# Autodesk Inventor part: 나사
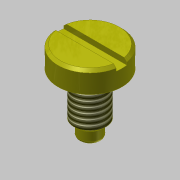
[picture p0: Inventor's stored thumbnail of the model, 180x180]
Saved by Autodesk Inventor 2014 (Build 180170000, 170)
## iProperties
Created: 2019-10
Part Number: 나사
Material: 스테인리스강
Document SubType Name: Modeling
Designer: mduedu
Density: 1 g/cm^3
Appearance: Yellow
Author: mduedu
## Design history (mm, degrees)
sketch "스케치1"
  geometry: L1 (0, 0)-(-6, 0); L2 (-6, 0)-(-6, -4); L3 (-6, -4)-(0, -4); L4 (0, -4)-(0, 0); L5 (0, -4)-(-3, -4); L6 (-3, -4)-(-3, -12.5); L7 (-3, -12.5)-(0, -12.5); L8 (0, -12.5)-(0, -4); L9 (0, -12.5)-(-2, -12.5); L10 (-2, -12.5)-(-2, -15); L11 (-2, -15)-(0, -15); L12 (0, -15)-(0, -12.5)
  constraints: 24 end point, 6 parallel, 3 horizontal, 3 perpendicular
  dimensions: "d0" = 15 distance between parallel lines of L11 L1; "d2" = 4 distance of L1.end L2.end; "d3" = 2.5 distance of L9.end L10.end; "d4" = 12 diameter of L2 L4; "d5" = 6 diameter of L6 L8; "d6" = 4 diameter of L10 L12
revolve "회전1" sketch "스케치1" stored, may be unused: angle "d7" = 90 deg
sketch "스케치2"
  geometry: L1 (2, -15)-(-2, -15) reference; L2 (-2, -15)-(-2, -12.5) reference; L3 (-2, -12.5)-(-3, -12.5) reference; L4 (-3, -12.5)-(-3, -4) reference; L5 (-3, -4)-(-6, -4) reference; L6 (-6, -4)-(-6, 0) reference; L7 (-6, 0)-(6, 0) reference; L8 (6, 0)-(6, -4) reference; L9 (6, -4)-(3, -4) reference; L10 (3, -4)-(3, -12.5) reference; L11 (3, -12.5)-(2, -12.5) reference; L12 (2, -12.5)-(2, -15) reference; L13 (0, 0)-(0, -15); L14 (-3, -4)-(-2.25, -4); L15 (-2.25, -4)-(-2.25, -4.5); L16 (-2.25, -4.5)-(-3, -4.5); L17 (-3, -4.5)-(-3, -4)
  constraints: 10 end point, 2 parallel, 1 horizontal, 1 midpoint, 1 perpendicular
  dimensions: "d8" = 4.5 diameter of L15 L13; "d10" = 0.5 distance between parallel lines of L16 L14
revolve "회전2" sketch "스케치2" stored, may be unused: angle "d11" = 90 deg
chamfer "모따기1" distance "d12" = 0.5; stored, may be unused: second distance "d13" = 2, angle "d14" = 45 deg
feature "스레드1" dims "d19" = 10, "d20" = 0
chamfer "모따기2" distance "d15" = 0.5; stored, may be unused: second distance "d16" = 2, angle "d17" = 45 deg
fillet "모깎기1" dims "d18" = 0.5
sketch "스케치3"
  geometry: L1 (-7.5, -1)-(7.5, -1); L2 (7.5, -1)-(7.5, 1); L3 (7.5, 1)-(-7.5, 1); L4 (-7.5, 1)-(-7.5, -1); L5 (-7.5, -1)-(7.5, 1); L6 (7.5, -1)-(-7.5, 1); 1 further point
  constraints: 12 end point, 2 midpoint, 2 parallel, 1 horizontal, 1 perpendicular
  dimensions: "d21" = 2 distance of L1.end L2.end; "d23" = 15 distance of L2.end L3.end
extrude "돌출1" cut sketch "스케치3" distance "d24" = 1; taper "d25" = 0 deg
node "솔리드1"
node "절단 모서리 투영1"
